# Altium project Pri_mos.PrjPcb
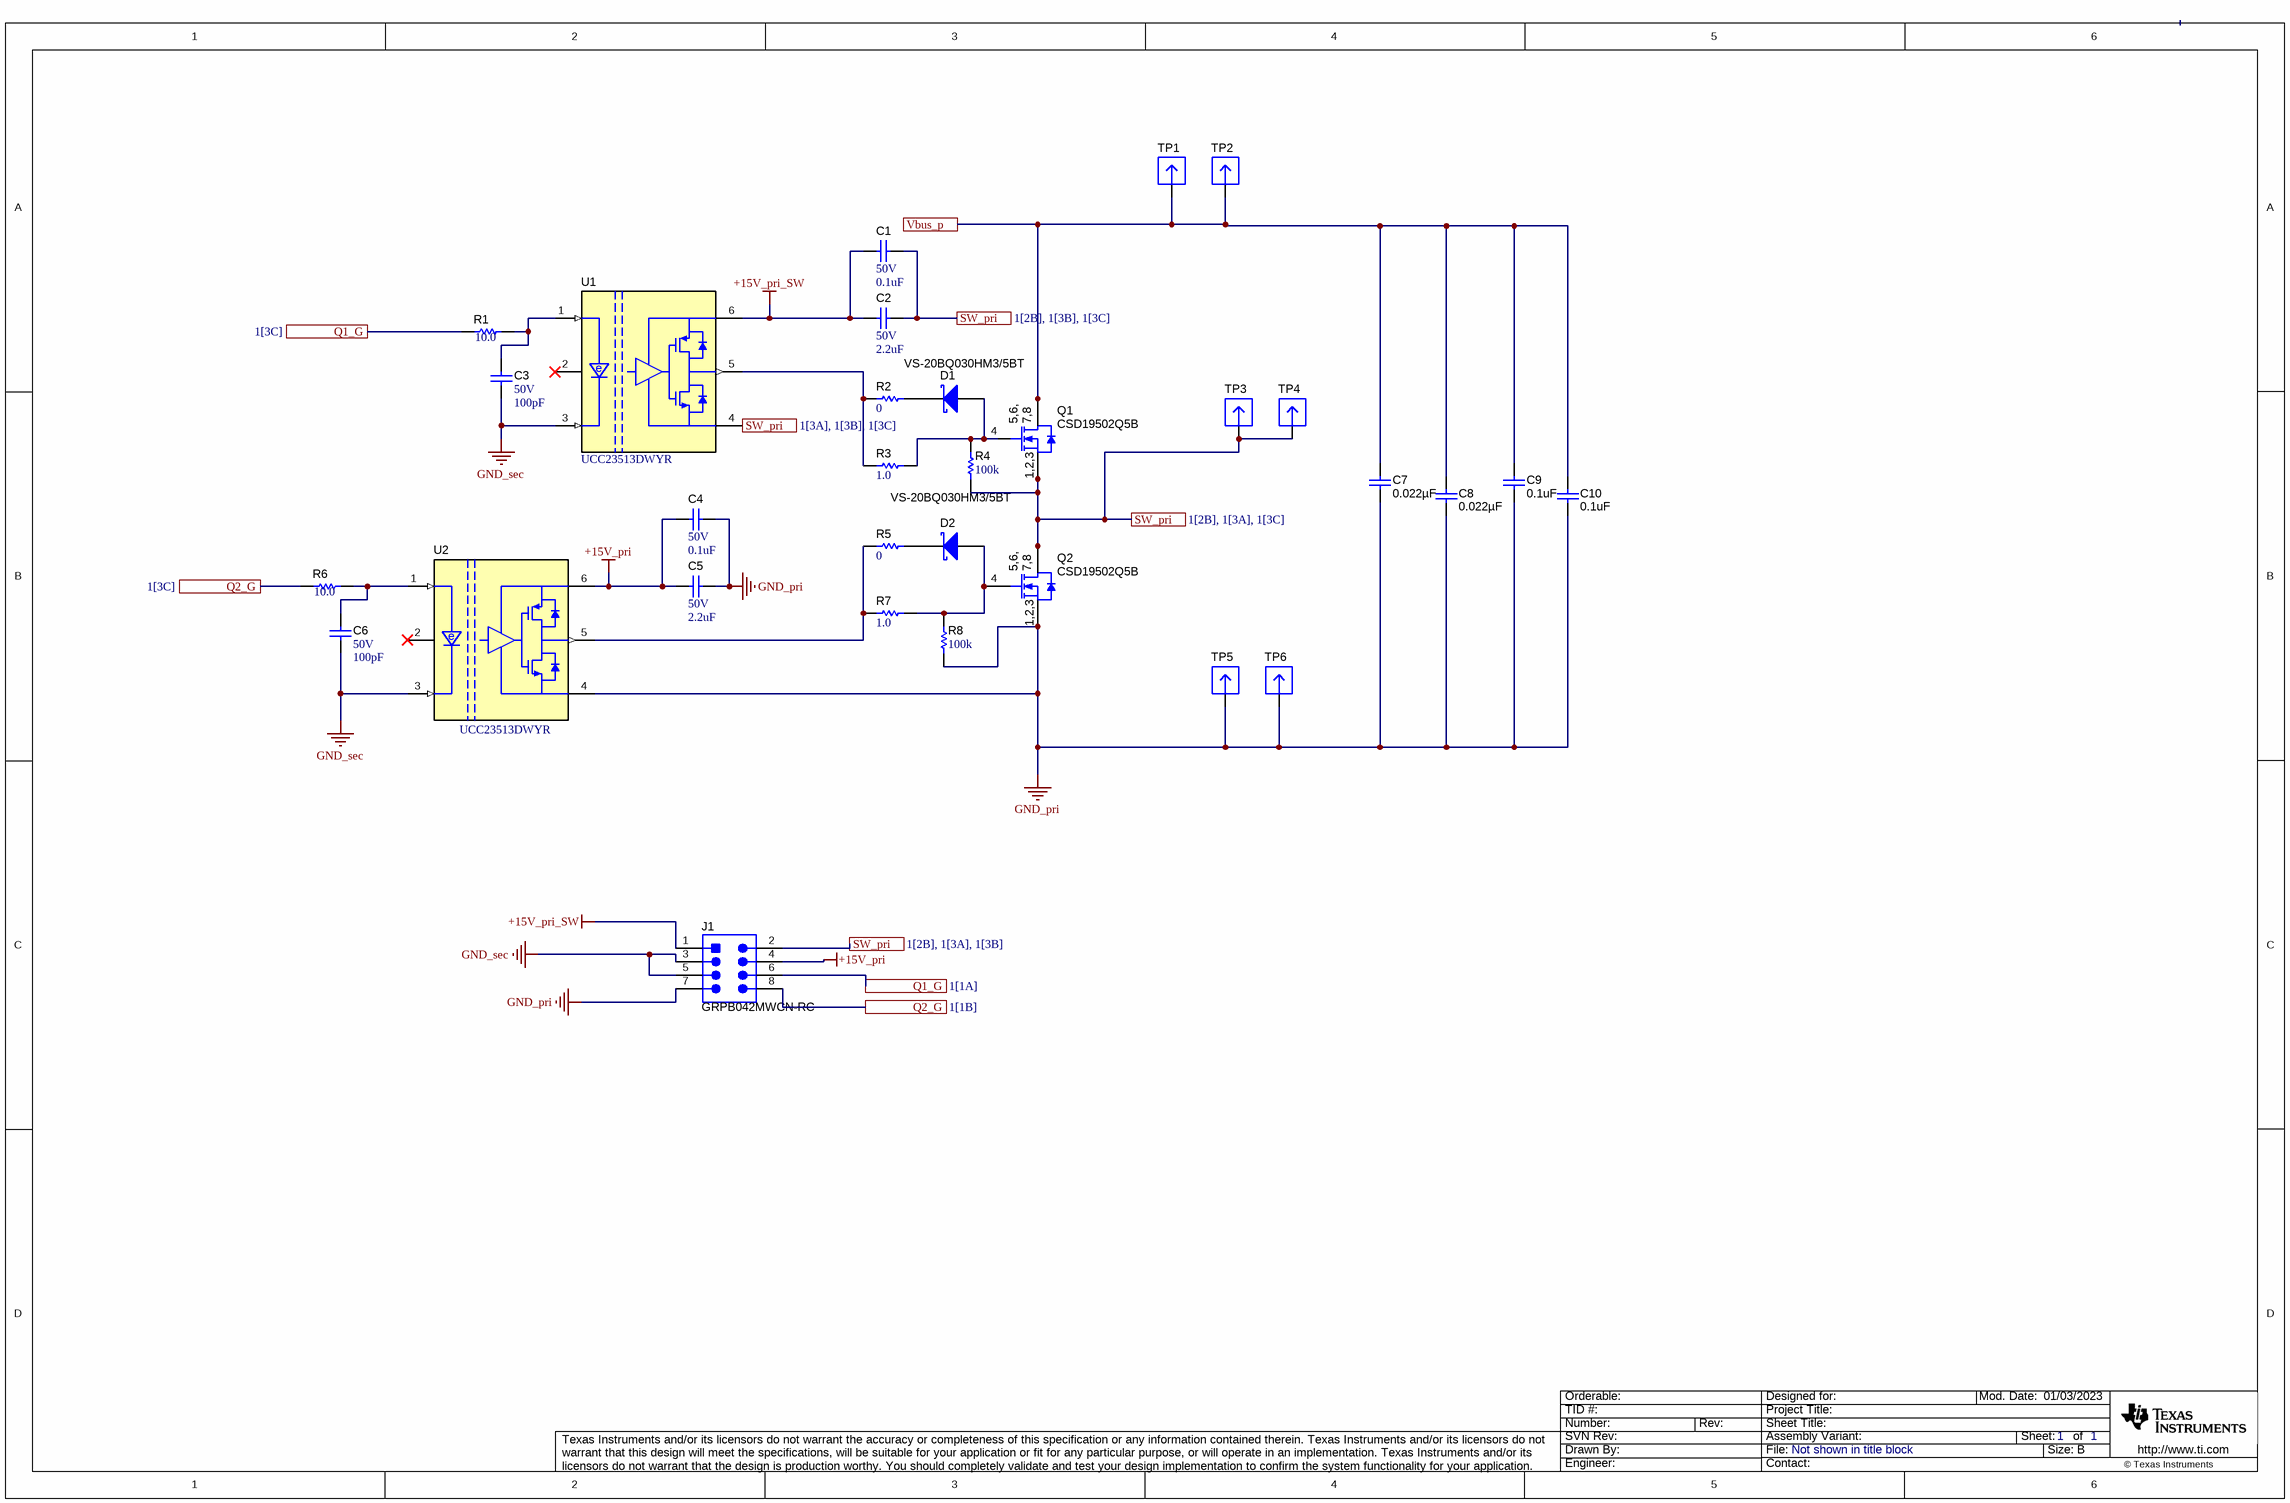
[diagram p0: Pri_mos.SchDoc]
1 sheet, 31 parts. Net scope: flat (ports and power ports of the same name join across sheets).
Board file: Pri.PcbDoc

## Sheet Pri_mos.SchDoc
size 431 x 279 mm; Date: Not shown in title block; ApprovedBy: Not shown in title block; CheckedBy: Not shown in title block; Author: Not shown in title block; CompanyName: Not shown in title block; Engineer: Not shown in title block; Organization: Not shown in title block; Address1: Not shown in title block; Address2: Not shown in title block; Address3: Not shown in title block; Address4: Not shown in title block; DocumentNumber: 2; Revision: Use project parameter SCH_Rev; SheetNumber: 1; SheetTotal: 1; PageSetup: Record=PageOptions¦CenterHorizontal=True¦CenterVertical=True¦PrintScale=1.00¦XCorrection=1.00¦YCorrection=1.00¦PrintKind=0¦BorderSize=5000000¦LeftOffset=0¦BottomOffset=0¦Orientation=2¦PaperLength=1000¦PaperWidth=1000¦Scale=100¦PaperSource=15¦PrintQuality=600¦MediaType=1¦DitherType=10¦PaperKind=Letter¦PrintScaleMode=1

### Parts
C1  VDC_V: 50V  ValueDisplayed: 0.1uF  [0603]  (hidden comment: C1608X5R1H104K080AA)
C2  VDC_V: 50V  ValueDisplayed: 2.2uF  [0603]  (hidden comment: GRM188R61H225KE11D)
C3  VDC_V: 50V  ValueDisplayed: 100pF  [0603]  (hidden comment: 06035A101FAT2A)
C4  VDC_V: 50V  ValueDisplayed: 0.1uF  [0603]  (hidden comment: C1608X5R1H104K080AA)
C5  VDC_V: 50V  ValueDisplayed: 2.2uF  [0603]  (hidden comment: GRM188R61H225KE11D)
C6  VDC_V: 50V  ValueDisplayed: 100pF  [0603]  (hidden comment: 06035A101FAT2A)
C7  ValueDisplayed: 0.022µF  [1206_190]  (hidden comment: C1206C223KDRACTU)
C8  ValueDisplayed: 0.022µF  [1206_190]  (hidden comment: C1206C223KDRACTU)
C9  ValueDisplayed: 0.1uF  [1812_254]  (hidden comment: C1812W104KDRACTU)
C10  ValueDisplayed: 0.1uF  [1812_254]  (hidden comment: C1812W104KDRACTU)
D1  VS-20BQ030HM3/5BT  [SMB]
D2  VS-20BQ030HM3/5BT  [SMB]
J1  GRPB042MWCN-RC  [Sullins_GRPB042MWCN]
Q1  CSD19502Q5B  [DNK0008A]
Q2  CSD19502Q5B  [DNK0008A]
R1  ValueDisplayed: 10.0  [0603]  (hidden comment: TNPW060310R0BEEA)
R2  ValueDisplayed: 0  [0805_HV]  (hidden comment: MCR10EZPJ000)
R3  ValueDisplayed: 1.0  [0805_HV]  (hidden comment: RC0805JR-071RL)
R4  ValueDisplayed: 100k  [0603]  (hidden comment: RT0603BRD07100KL)
R5  ValueDisplayed: 0  [0805_HV]  (hidden comment: MCR10EZPJ000)
R6  ValueDisplayed: 10.0  [0603]  (hidden comment: TNPW060310R0BEEA)
R7  ValueDisplayed: 1.0  [0805_HV]  (hidden comment: RC0805JR-071RL)
R8  ValueDisplayed: 100k  [0603]  (hidden comment: RT0603BRD07100KL)
TP1  3621-0-32-15-00-00-08-0  [Mill-Max_3621-0-32-xx-00-00-08-0]  (value not drawn)
TP2  3621-0-32-15-00-00-08-0  [Mill-Max_3621-0-32-xx-00-00-08-0]  (value not drawn)
TP3  3621-0-32-15-00-00-08-0  [Mill-Max_3621-0-32-xx-00-00-08-0]  (value not drawn)
TP4  3621-0-32-15-00-00-08-0  [Mill-Max_3621-0-32-xx-00-00-08-0]  (value not drawn)
TP5  3621-0-32-15-00-00-08-0  [Mill-Max_3621-0-32-xx-00-00-08-0]  (value not drawn)
TP6  3621-0-32-15-00-00-08-0  [Mill-Max_3621-0-32-xx-00-00-08-0]  (value not drawn)
U1  UCC23513DWYR  [DWY0006A]
U2  UCC23513DWYR  [DWY0006A]

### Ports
Q1_G (see 1[1A]), Q1_G (see 1[3C]), Q2_G (see 1[1B]), Q2_G (see 1[3C]), SW_pri (see 1[2B], 1[3A], 1[3B]), SW_pri (see 1[2B], 1[3A], 1[3C]), SW_pri (see 1[2B], 1[3B], 1[3C]), SW_pri (see 1[3A], 1[3B], 1[3C]), Vbus_p

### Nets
+15V_pri: C4.2 C5.2 J1.4 U2.6(Vout)
+15V_pri_SW: C1.2 C2.2 J1.1 U1.6(Vout)
GND_pri: C4.1 C5.1 C7.2 C8.2 C9.2 C10.2 J1.7 Q2.1(S) Q2.2(S) Q2.3(S) R8.1 TP5.1 TP6.1 U2.4(VSS)
GND_sec: C3.2 C6.2 J1.3 J1.5 U1.3(Cathode) U2.3(Cathode)
NetC1_1: C1.1 C2.1 J1.2 Q1.1(S) Q1.2(S) Q1.3(S) Q2.5(D) Q2.6(D) Q2.7(D) Q2.8(D) Q2.9(D) R4.1 TP3.1 TP4.1 U1.4(VSS) ; port SW_pri
NetC3_1: C3.1 R1.2 U1.1(Anode)
NetC6_1: C6.1 R6.2 U2.1(Anode)
NetC7_1: C7.1 C8.1 C9.1 C10.1 Q1.5(D) Q1.6(D) Q1.7(D) Q1.8(D) Q1.9(D) TP1.1 TP2.1 ; port Vbus_p
NetD1_1: D1.1(K) R2.2
NetD1_2: D1.2(A) Q1.4(G) R3.2 R4.2
NetD2_1: D2.1(K) R5.2
NetD2_2: D2.2(A) Q2.4(G) R7.2 R8.2
NetJ1_6: J1.6 R1.1 ; port Q1_G
NetJ1_8: J1.8 R6.1 ; port Q2_G
NetR2_1: R2.1 R3.1 U1.5(Vout)
NetR5_1: R5.1 R7.1 U2.5(Vout)

Not connected (* = marked no-connect by the designer): U1 2(NC)*; U2 2(NC)*

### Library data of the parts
C1 C4 = CMP-0007010-5: CAP, CERM, 0.1 uF, 50 V, +/- 10%, X5R, 0603; Manufacturer: TDK; TaMin_C: -55°C; ESR_ohm: 0.0296; Polarized: N; SizeAreaWB_mm2: 4.68; Value1: 0.0296 ohm; U/M: EA; Value: 0.1uF; TaMax_C: 85°C; SizeZ_mm: 1; SizeX_mm: 1.6; SizeY_mm: 0.8; SizeArea_mm2: 1.28; Cap_F: 100nF; IRMS_A: 9.7199dA; AEC Category: Q200
C2 C5 = CMP-0007353-5: CAP, CERM, 2.2 uF, 50 V, +/- 10%, X5R, 0603; Manufacturer: MuRata; TaMin_C: -55°C; Polarized: N; SizeAreaWB_mm2: 4.68; Value1: Unknown; U/M: EA; Value: 2.2uF; TaMax_C: 85°C; SizeZ_mm: 1; SizeX_mm: 1.6; SizeY_mm: 0.8; SizeArea_mm2: 1.28; Cap_F: 2.2µF; AEC Category: Q200
C3 C6 = CMP-0006762-4: CAP, CERM, 100 pF, 50 V, +/- 1%, C0G/NP0, 0603; Manufacturer: AVX; TaMin_C: -55°C; Polarized: N; SizeAreaWB_mm2: 4.68; Value1: Unknown; U/M: EA; TaMax_C: 125°C; SizeZ_mm: 1; SizeX_mm: 1.6; SizeY_mm: 0.8; SizeArea_mm2: 1.28; Value: 100pF; AEC Category: Q200
C7 C8 = CMP-0084048-1: CAP, CERM, 0.022 µF, 1000 V,+/- 10%, X7R, AEC-Q200 Grade 1, 1206; Manufacturer: Kemet; Polarized: N; CompType: Capacitor; Value: 0.022uF; U/M: EA; Cap_F: 22nF; VDC_V: 1kV; Value2: 1000V; TaMin_C: -55°C; TaMax_C: 125°C; Cap_Case: 1206; SizeArea_mm2: 5.12; SizeAreaWB_mm2: 10.92; SizeX_mm: 3.2; SizeY_mm: 1.6; SizeZ_mm: 1.9; AEC Category: Q200; AEC Qualified: Y; AEC Grade: 1
C9 C10 = CMP-0009326-2: CAP, CERM, 0.1 uF, 1000 V, +/- 10%, X7R, 1812; Manufacturer: Kemet; Polarized: N; Value: 0.1uF; U/M: EA; Cap_F: 100nF; Value1: Unknown; VDC_V: 1kV; Value2: 1000V; TaMin_C: -55°C; TaMax_C: 125°C; Cap_Case: 1812; AEC Category: Q200; SizeArea_mm2: 14.4; SizeAreaWB_mm2: 23.1; SizeX_mm: 4.5; SizeY_mm: 3.2; SizeZ_mm: 2.54
D1 D2 = CMP-0028909-2: Diode, Schottky, 30 V, 2 A, AEC-Q101, SMB; Manufacturer: Vishay-Semiconductor; Value1: 2A; Vf_V: 470mV; AEC Category: Q101; Green_Lifecycle: Not Set; SizeArea_mm2: 21.336; SizeZ_mm: 2.6; Value: 30V; Value2: 0.47V; SizeX_mm: 5.6; TJmax_C: 150°C; AEC Qualified: Y; Green_REACh: Incomplete; SizeAreaWB_mm2: 44.156; SizeY_mm: 3.81
J1 = CMP-0086278-1: Header, 1.27mm, 4x2, Gold, R/A, TH; Manufacturer: Sullins Connector Solutions; Current_A: 1A; Shrouded: N; Pitch_mm: 1.27; Voltage_V: 500V; Gender: Male; Row_Count: 2
Q1 Q2 = CMP-0000915-2: MOSFET, N-CH, 80 V, 100 A, DNK0008A (VSON-CLIP-8); Alternate Manufacturer: None; Manufacturer: Texas Instruments; SizeZ_mm: 1; ChType: N; Value2: 48 nC; VdsMax_V: 80V; SizeX_mm: 6; SizeY_mm: 5; Vgs_V: 20V; Value: 80V; SizeArea_mm2: 30; AEC Category: Q101; IdsMax_A: 100A; SizeAreaWB_mm2: 56; U/M: EA; QgTyp_nC: 48
R1 R6 = CMP-0025687-2: RES, 10.0, 0.1%, 0.1 W, 0603; Manufacturer: Vishay-Dale; Power_W: 100mW; TempCo: 25 ppm/C; Value_Code: 10R0; U/M: EA; Value: 10.0; EIA_Code: E192; Res_ohm: 10; SizeX_mm: 1.6; SizeY_mm: 0.8; SizeZ_mm: 1; Value2: 0.1W; SizeArea_mm2: 1.28; VDC_V: 75V; AEC Category: Q200
R2 R5 = CMP-0020802-2: RES, 0, 5%, 0.125 W, 0805; Manufacturer: Rohm; Power_W: 125mW; TempCo: 400 ppm/C; Value_Code: 0000; U/M: EA; Value: 0; EIA_Code: E24; SizeX_mm: 2; SizeY_mm: 1.25; SizeZ_mm: 1.45; Value2: 0.125W; SizeArea_mm2: 2.5; VDC_V: 150V; AEC Category: Q200
R3 R7 = CMP-0020811-2: RES, 1.0, 5%, 0.125 W, 0805; Manufacturer: Yageo America; Power_W: 125mW; TempCo: 200 ppm/C; Value_Code: 1R00; U/M: EA; Value: 1.0; EIA_Code: E24; Res_ohm: 1; SizeX_mm: 2; SizeY_mm: 1.25; SizeZ_mm: 1.45; Value2: 0.125W; SizeArea_mm2: 2.5; VDC_V: 150V; AEC Category: Q200
R4 R8 = CMP-0023630-3: RES, 100 k, 0.1%, 0.1 W, 0603; Manufacturer: Yageo America; Power_W: 100mW; TempCo: 25 ppm/C; U/M: EA; Value: 100k; EIA_Code: E192; SizeX_mm: 1.6; SizeY_mm: 0.8; SizeZ_mm: 1; Value2: 0.1W; SizeArea_mm2: 1.28; VDC_V: 75V; AEC Category: Q200
TP1-TP6 = CMP-0082316-1: PCB Pin, 0.04" DIA, Edge-Mount; Manufacturer: Mill-Max; CompType: PCB Pin; ContactFinish: Gold; Gender: Male; Row_Count: 1
U1 U2 = CMP-0081090-2: 5-kVRMS, 3-A Single Channel Isolated Gate Driver with Opto Compatible Input, DWY0006A (SOIC-6); Alternate Manufacturer: Texas Instruments; SizeAreaWB_mm2: 90.18; SizeZ_mm: 3.43; SizeX_mm: 11.5; SizeY_mm: 4.68; SizeArea_mm2: 53.82; CompType: IC; AEC Qualified: N; AEC Category: Q200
